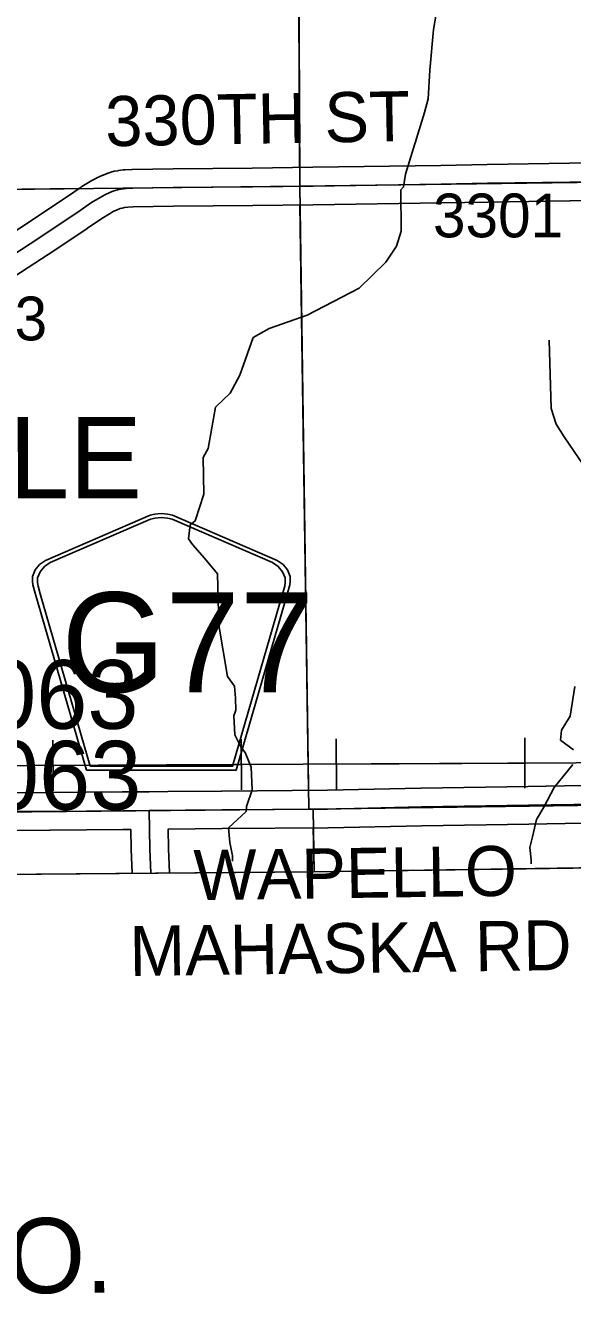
# Model space of a CAD drawing. Extents: x 23.6 to 68.7, y -63 to -29.
# Drawn here: x 46.344 to 47.219, y -58.387 to -56.351 of the extents above; entities that cross this region are included whole.
import ezdxf

# ---------------------------------------------------------------- set-up
doc = ezdxf.new("R2010")
doc.units = 0
for name, color, linetype in [('tdCoClipBndry', 7, 'Continuous'), ('tdCoCoAdjSecRdTxt', 7, 'Continuous'), ('tdCoCoBndry', 7, 'Continuous'), ('tdCoCoBndryTxt', 7, 'Continuous'), ('tdCoCorpTxt', 7, 'Continuous'), ('tdCoHydroRiver', 7, 'Continuous'), ('tdCoPipe', 7, 'Continuous'), ('tdCoSecRdNmbr', 7, 'Continuous'), ('tdCoSecRdTxt', 7, 'Continuous'), ('tdCoSecRteBand', 7, 'Continuous'), ('tdCoSecRteCL', 7, 'Continuous'), ('tdCoSectLine', 7, 'Continuous'), ('tdCoSectLinePart', 7, 'Continuous'), ('tdCoShieldCoRteHrd', 7, 'Continuous'), ('tdCoStrucPriMaintName', 7, 'Continuous'), ('tdCoSurfAsphalt', 7, 'Continuous'), ('tdCoSurfGravel', 7, 'Continuous'), ('tdCoTwpBndryShd', 7, 'Continuous')]:
    doc.layers.add(name, color=color, linetype=linetype)

msp = doc.modelspace()

# ---------------------------------------------------------------- linework, layer by layer
at = {"layer": 'tdCoClipBndry'}
msp.add_lwpolyline([(56.8227, -57.553), (51.8233, -57.6334), (46.8056, -57.7041), (45.8081, -57.7131), (44.8328, -57.735), (43.8446, -57.7356), (42.8125, -57.7502), (36.856, -57.8104), (34.8462, -57.8398), (33.8615, -57.8433), (32.8589, -57.8556), (32.833, -57.8525), (32.8013, -57.8383), (32.7717, -57.8067), (32.7614, -57.7827), (32.7577, -57.7569), (32.6839, -51.7283), (32.6474, -49.7276), (32.6233, -45.7459), (32.6113, -44.7492), (32.588, -43.7493), (32.587, -43.0064), (32.5923, -42.7484), (32.5183, -35.7733)], dxfattribs=at)
at = {"layer": 'tdCoCoBndry'}
for p, q in [((46.798, -57.6042), (45.8069, -57.6132)), ((45.8069, -57.6132), (46.798, -57.6042)), ((46.8045, -57.6042), (46.798, -57.6042)), ((46.798, -57.6042), (46.8045, -57.6042)), ((47.8017, -57.59), (46.8045, -57.6042)), ((46.8045, -57.6042), (47.8017, -57.59))]:
    msp.add_line(p, q, dxfattribs=at)
for points in [[(35.8551, -57.7251), (36.8548, -57.7104), (37.8632, -57.702), (38.8607, -57.6881), (39.821, -57.6811), (40.8084, -57.671), (40.8282, -57.6709), (41.8142, -57.6606), (42.8114, -57.6502), (43.828, -57.6382), (43.8439, -57.6356), (44.8231, -57.6351), (44.8305, -57.6351), (45.7951, -57.6134), (45.8065, -57.6132), (46.7976, -57.6042), (46.8042, -57.6042), (47.8013, -57.59), (48.8, -57.5731), (49.8013, -57.5613), (50.7973, -57.5472), (51.8219, -57.5335), (52.8221, -57.5189)], [(52.8224, -57.5189), (51.8222, -57.5335), (50.7977, -57.5472), (49.8017, -57.5614), (48.8003, -57.5731), (47.8017, -57.59), (46.8045, -57.6042), (46.798, -57.6042), (45.8069, -57.6132), (45.7954, -57.6134), (44.8309, -57.6351), (44.8234, -57.6351), (43.8442, -57.6356), (43.8283, -57.6383), (42.8118, -57.6502), (41.8146, -57.6606), (40.8286, -57.6709), (40.8087, -57.671), (39.8213, -57.6811), (38.8611, -57.6881), (37.8635, -57.702), (36.8552, -57.7104), (35.8554, -57.7251)], [(52.8224, -57.5189), (51.8222, -57.5335), (50.7977, -57.5472), (49.8017, -57.5614), (48.8003, -57.5731), (47.8017, -57.59), (46.8045, -57.6042), (46.798, -57.6042), (45.8069, -57.6132), (45.7954, -57.6134), (44.8309, -57.6351), (44.8317, -57.735), (44.8328, -57.735), (45.8081, -57.7131), (46.8056, -57.7041), (51.8233, -57.6334), (56.8227, -57.553)]]:
    msp.add_lwpolyline(points, dxfattribs=at)
at = {"layer": 'tdCoHydroRiver'}
for points in [[(47.0148, -56.2564), (46.9969, -56.3576), (46.9913, -56.4224), (46.9887, -56.4682), (46.9826, -56.4904), (46.9521, -56.5886), (46.9492, -56.6091), (46.9445, -56.6139), (46.9452, -56.6802), (46.9376, -56.704), (46.9205, -56.7294), (46.8783, -56.7709), (46.7951, -56.8145), (46.7338, -56.8356), (46.7087, -56.8501), (46.6873, -56.9104), (46.6718, -56.9389), (46.6483, -56.9613), (46.6364, -57.0277), (46.6287, -57.042), (46.6293, -57.1004), (46.6156, -57.1432), (46.6078, -57.1496), (46.6049, -57.1717), (46.6113, -57.1811), (46.6305, -57.203), (46.6513, -57.2281), (46.6537, -57.3101), (46.6673, -57.3921), (46.6785, -57.4077), (46.6803, -57.4266), (46.6805, -57.4456), (46.6774, -57.4551), (46.6793, -57.4851), (46.689, -57.5055), (46.6954, -57.5133), (46.7052, -57.5369), (46.7071, -57.5732), (46.698, -57.6001), (46.6975, -57.6076)], [(47.1823, -56.8544), (47.1851, -56.9633), (47.1933, -56.9885), (47.2061, -57.0089), (47.2382, -57.0559)], [(47.2231, -57.4081), (47.2157, -57.4555), (47.2018, -57.4778), (47.2004, -57.4936), (47.2211, -57.5091)], [(47.2197, -57.5328), (47.1901, -57.5694), (47.1737, -57.6007)], [(47.1737, -57.6007), (47.1617, -57.6206), (47.1552, -57.6485), (47.151, -57.6656), (47.1531, -57.6849), (47.1531, -57.6913)], [(46.6975, -57.6076), (46.6692, -57.6338), (46.6713, -57.6573), (46.6756, -57.6787), (46.6756, -57.6873)]]:
    msp.add_lwpolyline(points, dxfattribs=at)
at = {"layer": 'tdCoPipe'}
for p, q in [((46.388, -57.4939), (46.3883, -57.5746)), ((46.6893, -57.4924), (46.6897, -57.573)), ((46.8415, -57.4917), (46.8419, -57.5724)), ((47.1429, -57.4902), (47.1433, -57.5708))]:
    msp.add_line(p, q, dxfattribs=at)
for points in [[(53.0685, -56.591), (50.7015, -56.6132), (50.7179, -57.2247), (50.5989, -57.2241), (49.8578, -56.9776), (49.7137, -56.9708), (49.1168, -57.0055), (49.0002, -57.0742), (48.9111, -57.2115), (48.8699, -57.2459), (48.815, -57.2528), (48.1221, -57.267), (48.1221, -57.267), (48.0398, -57.2807), (47.9849, -57.2876), (47.9163, -57.3083), (47.7174, -57.528), (47.6625, -57.5281), (46.0227, -57.536), (46.016, -57.7076)], [(46.6895, -57.5328), (46.3881, -57.5342)], [(47.1431, -57.5306), (46.8417, -57.532)]]:
    msp.add_lwpolyline(points, dxfattribs=at)
at = {"layer": 'tdCoSecRteBand'}
for points in [[(46.2825, -56.7094), (46.3475, -56.6671), (46.3928, -56.6369), (46.3928, -56.6368), (46.3929, -56.6368), (46.4098, -56.6256), (46.433, -56.6096), (46.4337, -56.6092), (46.4343, -56.6088), (46.4478, -56.6005), (46.4485, -56.6001), (46.4492, -56.5997), (46.4567, -56.5956), (46.4576, -56.5952), (46.4584, -56.5948), (46.4666, -56.591), (46.4675, -56.5906), (46.4685, -56.5902), (46.4751, -56.5877), (46.4758, -56.5874), (46.4765, -56.5872), (46.4823, -56.5853), (46.4842, -56.5847), (46.4861, -56.5843), (46.4921, -56.5833), (46.4926, -56.5831), (46.4932, -56.5831), (46.5007, -56.582), (46.5022, -56.5818), (46.5037, -56.5817), (46.5143, -56.5812), (46.5148, -56.5812), (46.5152, -56.5812), (46.5802, -56.5803), (46.5803, -56.5803), (46.5804, -56.5803), (46.7071, -56.579), (46.8039, -56.5779), (47.0089, -56.5749), (47.0826, -56.5734), (47.0827, -56.5734), (47.0828, -56.5734), (47.2144, -56.5715), (47.3068, -56.5699)], [(47.3077, -56.6299), (47.2154, -56.6315), (47.2153, -56.6315), (47.2153, -56.6315), (47.0838, -56.6334), (47.0101, -56.6349), (47.01, -56.6349), (47.0099, -56.6349), (46.8047, -56.6379), (46.8046, -56.6379), (46.8046, -56.6379), (46.7078, -56.639), (46.7077, -56.639), (46.7077, -56.639), (46.581, -56.6402), (46.5165, -56.6412), (46.5078, -56.6416), (46.5024, -56.6424), (46.4989, -56.643), (46.4957, -56.644), (46.4908, -56.6459), (46.4845, -56.6488), (46.4785, -56.6521), (46.4664, -56.6595), (46.4435, -56.6752), (46.4433, -56.6754), (46.4431, -56.6755), (46.4261, -56.6868), (46.3807, -56.7171), (46.3805, -56.7172), (46.3804, -56.7173), (46.315, -56.7598)], [(46.3063, -57.5781), (46.3829, -57.5776), (46.4996, -57.5766), (46.4996, -57.5766), (46.4996, -57.5766), (46.5418, -57.5762), (46.5717, -57.5757), (46.5717, -57.576), (46.6581, -57.5753), (46.6582, -57.5753), (46.6582, -57.5753), (46.8272, -57.574), (46.9769, -57.5706), (46.977, -57.5706), (46.9771, -57.5706), (47.1487, -57.568), (47.2935, -57.5654)], [(46.5146, -57.7067), (46.5132, -57.6687), (46.5132, -57.6684), (46.5132, -57.6681), (46.5127, -57.6365), (46.5124, -57.6365), (46.5001, -57.6366), (46.3834, -57.6376), (46.3833, -57.6376), (46.3833, -57.6376), (46.3067, -57.6381)], [(47.2944, -57.6254), (47.1497, -57.628), (47.1497, -57.628), (47.1496, -57.628), (46.9782, -57.6306), (46.8283, -57.634), (46.8281, -57.634), (46.8279, -57.634), (46.6586, -57.6353), (46.5727, -57.636), (46.5732, -57.6668), (46.5746, -57.7059), (46.5746, -57.7062)]]:
    msp.add_lwpolyline(points, dxfattribs=at)
at = {"layer": 'tdCoSecRteCL'}
for points in [[(46.2987, -56.7346), (46.364, -56.6922), (46.4094, -56.6618), (46.4265, -56.6505), (46.45, -56.6344), (46.4635, -56.6261), (46.471, -56.622), (46.4792, -56.6182), (46.4857, -56.6157), (46.4915, -56.6139), (46.4975, -56.6128), (46.505, -56.6117), (46.5157, -56.6112), (46.5807, -56.6102), (46.7074, -56.609), (46.8042, -56.6079), (47.0095, -56.6049), (47.0833, -56.6034), (47.2149, -56.6015), (47.3073, -56.5999)], [(46.5422, -57.6062), (46.6584, -57.6053), (46.8276, -57.604), (46.9776, -57.6006), (47.1492, -57.598), (47.294, -57.5954), (47.4487, -57.5937), (47.5916, -57.5924), (47.6852, -57.5907), (47.7006, -57.5909), (47.7105, -57.5905), (47.7107, -57.5905), (47.718, -57.5894), (47.7291, -57.5875), (47.7368, -57.5856), (47.7486, -57.5813), (47.7602, -57.5757), (47.7717, -57.5689), (47.7822, -57.5611), (47.785, -57.5585)], [(45.7934, -57.6134), (45.8252, -57.6128), (45.853, -57.6123), (45.9221, -57.6111), (45.9519, -57.6106), (45.9527, -57.6106), (45.9997, -57.6106), (46.0011, -57.6106), (46.1609, -57.6089), (46.3065, -57.6081), (46.3831, -57.6076), (46.4999, -57.6066), (46.5422, -57.6062)], [(46.5446, -57.7065), (46.5432, -57.6676), (46.5422, -57.6062)]]:
    msp.add_lwpolyline(points, dxfattribs=at)
at = {"layer": 'tdCoSectLine'}
for points in [[(46.7789, -55.6148), (46.7829, -56.6081)], [(46.7829, -56.6081), (47.7923, -56.5945)], [(45.7924, -56.619), (46.7829, -56.6081)], [(46.7829, -56.6081), (46.7976, -57.6042)], [(45.8065, -57.6132), (46.7976, -57.6042)], [(46.7976, -57.6042), (46.8042, -57.6042)], [(46.8042, -57.6042), (47.8013, -57.59)], [(46.8042, -57.6042), (46.8058, -57.7041)]]:
    msp.add_lwpolyline(points, dxfattribs=at)
at = {"layer": 'tdCoSectLinePart'}
for points in [[(46.779, -55.6454), (46.7827, -56.5781)], [(45.7924, -56.619), (46.4292, -56.612)], [(46.7833, -56.6378), (46.7972, -57.5742)], [(46.8047, -57.6341), (46.8058, -57.7041)]]:
    msp.add_lwpolyline(points, dxfattribs=at)
at = {"layer": 'tdCoShieldCoRteHrd'}
for points in [[(46.4418, -57.5417), (46.3598, -57.2588), (46.3559, -57.2457), (46.3552, -57.2398), (46.3552, -57.232), (46.3595, -57.2217), (46.3667, -57.2132), (46.3763, -57.2065), (46.5436, -57.1342), (46.5511, -57.1325), (46.5615, -57.1316), (46.5719, -57.1325), (46.5795, -57.1342), (46.7467, -57.2065), (46.7563, -57.2132), (46.7636, -57.2217), (46.7678, -57.232), (46.7678, -57.2398), (46.7671, -57.2457), (46.7632, -57.2588), (46.6813, -57.5417)], [(46.4476, -57.5354), (46.3679, -57.2601), (46.3642, -57.2475), (46.3635, -57.2419), (46.3635, -57.2343), (46.3675, -57.2245), (46.3745, -57.2163), (46.3837, -57.2099), (46.5443, -57.1404), (46.5515, -57.1389), (46.5615, -57.138), (46.5715, -57.1389), (46.5787, -57.1404), (46.7393, -57.2099), (46.7485, -57.2163), (46.7555, -57.2245), (46.7596, -57.2343), (46.7596, -57.2419), (46.7589, -57.2475), (46.7552, -57.2601), (46.6754, -57.5354)]]:
    msp.add_lwpolyline(points, close=True, dxfattribs=at)
at = {"layer": 'tdCoSurfAsphalt'}
msp.add_lwpolyline([(45.5468, -57.6205), (45.5975, -57.6192), (45.6594, -57.6177), (45.7828, -57.6136), (45.7934, -57.6134), (45.8252, -57.6128), (45.853, -57.6123), (45.9221, -57.6111), (45.9519, -57.6106), (45.9527, -57.6106), (45.9997, -57.6106), (46.0011, -57.6106), (46.1609, -57.6089), (46.3065, -57.6081), (46.3831, -57.6076), (46.4999, -57.6066), (46.5422, -57.6062), (46.6584, -57.6053), (46.8276, -57.604), (46.9776, -57.6006), (47.1492, -57.598), (47.294, -57.5954)], dxfattribs=at)
at = {"layer": 'tdCoSurfGravel'}
for points in [[(46.2987, -56.7346), (46.364, -56.6922), (46.4094, -56.6618), (46.4265, -56.6505), (46.45, -56.6344), (46.4635, -56.6261), (46.471, -56.622), (46.4792, -56.6182), (46.4857, -56.6157), (46.4915, -56.6139), (46.4975, -56.6128), (46.505, -56.6117), (46.5157, -56.6112), (46.5807, -56.6102), (46.7074, -56.609), (46.8042, -56.6079), (47.0095, -56.6049), (47.0833, -56.6034), (47.2149, -56.6015), (47.3073, -56.5999)], [(46.5446, -57.7065), (46.5432, -57.6676), (46.5422, -57.6062)]]:
    msp.add_lwpolyline(points, dxfattribs=at)
at = {"layer": 'tdCoTwpBndryShd'}
msp.add_lwpolyline([(52.8221, -57.5189), (51.8219, -57.5335), (50.7973, -57.5472), (49.8013, -57.5613), (48.8, -57.5731), (47.8013, -57.59), (46.8042, -57.6042), (46.7976, -57.6042), (45.8065, -57.6132), (45.7951, -57.6134), (44.8305, -57.6351), (44.8231, -57.6351), (43.8439, -57.6356), (43.828, -57.6382), (42.8114, -57.6502), (41.8142, -57.6606), (40.8282, -57.6709), (40.8084, -57.671), (39.821, -57.6811), (38.8607, -57.6881), (37.8632, -57.702), (36.8548, -57.7104), (35.8551, -57.7251)], dxfattribs=at)

# ---------------------------------------------------------------- texts
at = {"layer": 'tdCoCoAdjSecRdTxt'}
for s, p in [('WAPELLO', (46.6137, -57.7497)), ('MAHASKA RD', (46.511, -57.8711))]:
    msp.add_text(s, height=0.08, rotation=0.8024, dxfattribs=at).set_placement(p)
at = {"layer": 'tdCoCoBndryTxt'}
msp.add_text('WAPELLO CO.', height=0.12, rotation=0.5186, dxfattribs=at).set_placement((45.3791, -58.3869))
at = {"layer": 'tdCoCorpTxt'}
msp.add_text('EDDYVILLE', height=0.13, rotation=0.0346, dxfattribs=at).set_placement((45.5738, -57.1077))
at = {"layer": 'tdCoSecRdNmbr'}
for s, rotation, p in [('3301', 0.0364, (46.9962, -56.6899)), ('3203', 0.0358, (46.1706, -56.8547))]:
    msp.add_text(s, height=0.07, rotation=rotation, dxfattribs=at).set_placement(p)
at = {"layer": 'tdCoSecRdTxt'}
msp.add_text('330TH ST', height=0.08, rotation=0.9952, dxfattribs=at).set_placement((46.4724, -56.5443))
at = {"layer": 'tdCoShieldCoRteHrd'}
msp.add_text('G77', height=0.16, dxfattribs=at).set_placement((46.4017, -57.4175))
at = {"layer": 'tdCoStrucPriMaintName'}
for s, p in [('90539R063', (45.7643, -57.4757)), ('90539R063', (45.7643, -57.4757)), ('90539R063', (45.7643, -57.4757)), ('90539L063', (45.7933, -57.6049)), ('90539L063', (45.7933, -57.6049)), ('90539L063', (45.7933, -57.6049))]:
    msp.add_text(s, height=0.11, dxfattribs=at).set_placement(p)

doc.saveas('drawing.dxf')
